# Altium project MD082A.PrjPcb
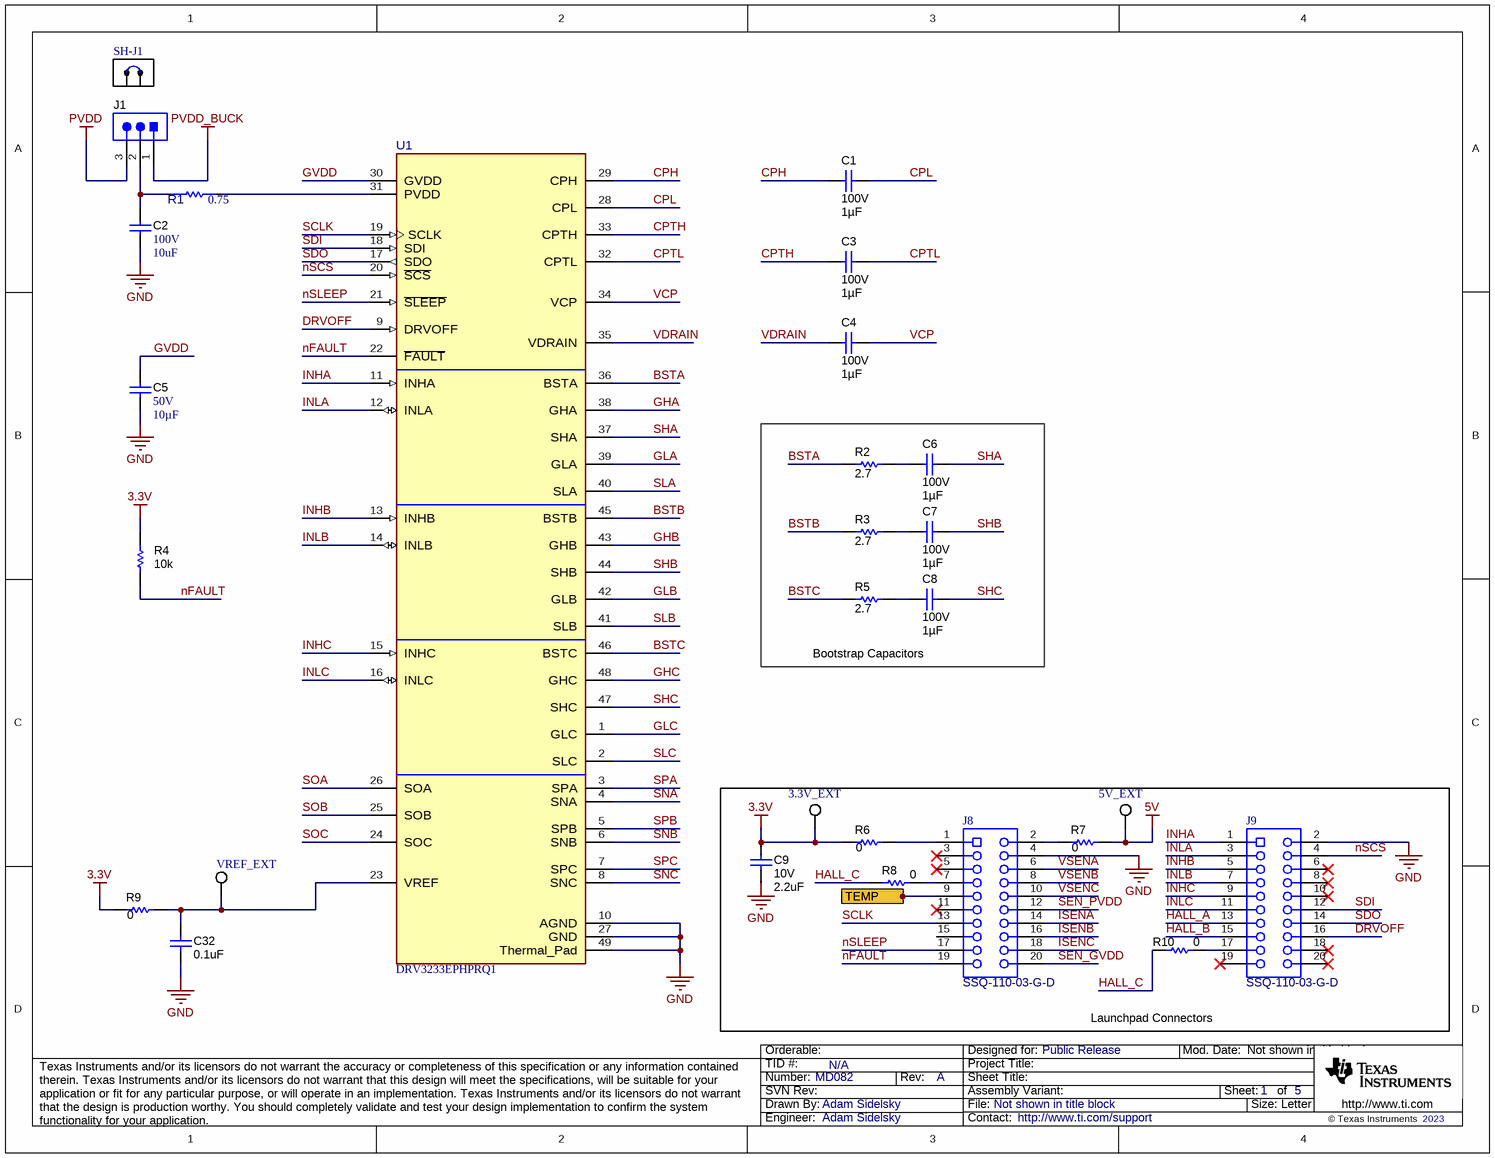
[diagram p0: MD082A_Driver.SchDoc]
CopyrightYear: 2023; DrawnBy: Adam Sidelsky; PCB_Layout: Adam Sidelsky; PCB_Rev: A; PRJ_Customer: Public Release; PRJ_Engineer: Adam Sidelsky; PRJ_Number: MD082; SCH_Rev: A; TechSupport: http://www.ti.com/support; TID: N/A
5 sheets, 201 parts. Net scope: global (net labels, ports and power ports of the same name join across sheets).
Board file: MD082A.PcbDoc
Sheets:
  MD082A_Driver.SchDoc
  MD082A_HalfBridges.SchDoc
  MD082A_Power.SchDoc
  MD082A_Hardware.SchDoc
  MD082A_SenseFeedback.SchDoc

## Sheet MD082A_Driver.SchDoc
size Letter; Date: Not shown in title block; ApprovedBy: Not shown in title block; CheckedBy: Not shown in title block; Author: Not shown in title block; CompanyName: Not shown in title block; Engineer: Not shown in title block; Organization: Not shown in title block; Address1: Not shown in title block; Address2: Not shown in title block; Address3: Not shown in title block; Address4: Not shown in title block; DocumentNumber: 1; Revision: Use project parameter SCH_Rev; SheetNumber: 1; SheetTotal: 5; PageSetup: Record=PageOptions¦CenterHorizontal=True¦CenterVertical=True¦PrintScale=1.00¦XCorrection=1.00¦YCorrection=1.00¦PrintKind=0¦BorderSize=5000000¦LeftOffset=0¦BottomOffset=0¦Orientation=2¦PaperLength=1000¦PaperWidth=1000¦Scale=100¦PaperSource=15¦PrintQuality=600¦MediaType=1¦DitherType=10¦PaperKind=Letter¦PrintScaleMode=1

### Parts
3.3V_EXT  5015  [Testpoint_Keystone_Miniature]  (value not drawn)
5V_EXT  5015  [Testpoint_Keystone_Miniature]  (value not drawn)
C1  VDC_V: 100V  Cap_F: 1µF  [0805_150]  (hidden comment: KAF21KR72A105KU)
C2  VDC_V: 100V  ValueDisplayed: 10uF  [2220_280L]  (hidden comment: CGA9N3X7S2A106K230KE)
C3  VDC_V: 100V  Cap_F: 1µF  [0805_150]  (hidden comment: KAF21KR72A105KU)
C4  VDC_V: 100V  Cap_F: 1µF  [0805_150]  (hidden comment: KAF21KR72A105KU)
C5  VDC_V: 50V  ValueDisplayed: 10µF  [1210_270L]  (hidden comment: CL32B106KBJNNWE)
C6  VDC_V: 100V  Cap_F: 1µF  [0805_150]  (hidden comment: KAF21KR72A105KU)
C7  VDC_V: 100V  Cap_F: 1µF  [0805_150]  (hidden comment: KAF21KR72A105KU)
C8  VDC_V: 100V  Cap_F: 1µF  [0805_150]  (hidden comment: KAF21KR72A105KU)
C9  VDC_V: 10V  ValueDisplayed: 2.2uF  [0402L]  (hidden comment: C1005X5R1A225K050BC)
C32  ValueDisplayed: 0.1uF  [0603L]  (hidden comment: C0603C104J4RAC7867)
J1  61300311121  [WURTH_61300311121]  (value not drawn)
J8  SSQ-110-03-G-D  [Samtec_SSQ-110-03-x-D]
J9  SSQ-110-03-G-D  [Samtec_SSQ-110-03-x-D]
R1  value 0.75  [FP-RL1220S-R75-F_0805-IPC_A]  (hidden comment: RL1220S-R75-F)
R2  ValueDisplayed: 2.7  [0805L]  (hidden comment: CRCW08052R70JNEA)
R3  ValueDisplayed: 2.7  [0805L]  (hidden comment: CRCW08052R70JNEA)
R4  value 10k  [0603L]  (hidden comment: CRCW060310K0JNEA)
R5  ValueDisplayed: 2.7  [0805L]  (hidden comment: CRCW08052R70JNEA)
R6  ValueDisplayed: 0  [0603L]  (hidden comment: RCS06030000Z0EA)
R7  ValueDisplayed: 0  [0603L]  (hidden comment: RCS06030000Z0EA)
R8  ValueDisplayed: 0  [0603L]  (hidden comment: RCS06030000Z0EA)
R9  ValueDisplayed: 0  [0603L]  (hidden comment: RCS06030000Z0EA)
R10  ValueDisplayed: 0  [0603L]  (hidden comment: RCS06030000Z0EA)
SH-J1  SNT-100-BK-G  [SNT-100-BK-G]  (value not drawn)
U1  DRV3233EPHPRQ1  [0-MFG]
VREF_EXT  5015  [Testpoint_Keystone_Miniature]  (value not drawn)

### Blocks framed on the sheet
Bootstrap Capacitors: C6-C8 R2 R3 R5
Launchpad Connectors: 3.3V_EXT 5V_EXT C9 J8 J9 R6-R8 R10

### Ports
TEMP (out)

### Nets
3.3V: 3.3V_EXT.1 C9.2 R4.1 R6.1 R9.1
5V: 5V_EXT.1 R7.2
GND: C2.2 C5.2 C9.1 C32.2 J8.4 J9.2 U1.10(AGND) U1.27(GND) U1.49(Thermal_Pad)
GVDD: C5.1 U1.30(GVDD)
PVDD: J1.3
PVDD_BUCK: J1.1
BSTA: R2.2 U1.36(BSTA)
BSTB: R3.2 U1.45(BSTB)
BSTC: R5.2 U1.46(BSTC)
CPH: C1.1 U1.29(CPH)
CPL: C1.2 U1.28(CPL)
CPTH: C3.1 U1.33(CPTH)
CPTL: C3.2 U1.32(CPTL)
DRVOFF: J9.16 U1.9(DRVOFF)
GHA: U1.38(GHA)
GHB: U1.43(GHB)
GHC: U1.48(GHC)
GLA: U1.39(GLA)
GLB: U1.42(GLB)
GLC: U1.1(GLC)
HALL_A: J9.13
HALL_B: J9.15
HALL_C: R8.1 R10.1
INHA: J9.1 U1.11(INHA)
INHB: J9.5 U1.13(INHB)
INHC: J9.9 U1.15(INHC)
INLA: J9.3 U1.12(INLA)
INLB: J9.7 U1.14(INLB)
INLC: J9.11 U1.16(INLC)
ISENA: J8.14
ISENB: J8.16
ISENC: J8.18
nFAULT: J8.19 R4.2 U1.22(~{FAULT})
nSCS: J9.4 U1.20(~{SCS})
nSLEEP: J8.17 U1.21(~{SLEEP})
SCLK: J8.13 U1.19(SCLK)
SDI: J9.12 U1.18(SDI)
SDO: J9.14 U1.17(SDO)
SEN_GVDD: J8.20
SEN_PVDD: J8.12
SHA: C6.1 U1.37(SHA)
SHB: C7.1 U1.44(SHB)
SHC: C8.1 U1.47(SHC)
SLA: U1.40(SLA)
SLB: U1.41(SLB)
SLC: U1.2(SLC)
SNA: U1.4(SNA)
SNB: U1.6(SNB)
SNC: U1.8(SNC)
SOA: U1.26(SOA)
SOB: U1.25(SOB)
SOC: U1.24(SOC)
SPA: U1.3(SPA)
SPB: U1.5(SPB)
SPC: U1.7(SPC)
TEMP: J8.9 ; port TEMP
VCP: C4.1 U1.34(VCP)
VDRAIN: C4.2 U1.35(VDRAIN)
VSENA: J8.6
VSENB: J8.8
VSENC: J8.10
NetC2_1: C2.1 J1.2 R1.1
NetC6_2: C6.2 R2.1
NetC7_2: C7.2 R3.1
NetC8_2: C8.2 R5.1
NetC32_1: C32.1 R9.2 U1.23(VREF) VREF_EXT.1
NetJ8_1: J8.1 R6.2
NetJ8_2: J8.2 R7.1
NetJ8_7: J8.7 R8.2
NetJ9_17: J9.17 R10.2
NetR1_2: R1.2 U1.31(PVDD)

Not connected (* = marked no-connect by the designer): J8 3* 5* 11* 15; J9 6* 8* 10* 18* 19* 20*

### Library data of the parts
3.3V_EXT 5V_EXT VREF_EXT = CMP-0055152-2: Test Point, Miniature, SMT; Manufacturer: Keystone Electronics; CT: TRUE; Green_Lifecycle: Active; Green_REACh: Passed; CNHeader: FALSE
C1 C3 C4 C6-C8 = CMP-0861070-2: CAP, CERM, 1 µF, 100 V,+/- 10%, X7R, AEC-Q200 Grade 1, 0805; Manufacturer: AVX; SizeZ_mm: 1.5; Polarized: N; TaMax_C: 125°C; TaMin_C: -55°C; Value: 1uF; AEC Qualified: Y; U/M: EA; AEC Grade: 1; Cap_Case: 0805; SizeX_mm: 2; SizeArea_mm2: 2.5; SizeAreaWB_mm2: 6.75; AEC Category: Q200; SizeY_mm: 1.25
C2 = CMP-0064964-2: CAP, CERM, 10 uF, 100 V,+/- 10%, X7S, AEC-Q200 Grade 1, 2220; Manufacturer: TDK; TaMin_C: -55°C; Polarized: N; SizeAreaWB_mm2: 53.9; Value1: Unknown; U/M: EA; Value: 10uF; TaMax_C: 125°C; SizeZ_mm: 2.8; SizeX_mm: 5.7; SizeY_mm: 5; Cap_Case: 2220; SizeArea_mm2: 28.5; AEC Qualified: Y; Cap_F: 10µF; AEC Grade: 1; AEC Category: Q200
C5 = CMP-0079201-1: CAP, CERM, 10 µF, 50 V,+/- 10%, X7R, 1210; Manufacturer: Samsung Electro-Mechanics; TaMin_C: -55°C; ESR_ohm: 5m; Polarized: N; SizeAreaWB_mm2: 14.7; Value1: 0.005 ohm; U/M: EA; Value: 10uF; TaMax_C: 125°C; SizeZ_mm: 2.7; SizeX_mm: 3.2; SizeY_mm: 2.5; Cap_Case: 1210; SizeArea_mm2: 8; AEC Category: Q200
C9 = CMP-0006263-2: CAP, CERM, 2.2 uF, 10 V, +/- 10%, X5R, 0402; Manufacturer: TDK; TaMin_C: -55°C; Polarized: N; SizeAreaWB_mm2: 3; Value1: Unknown; U/M: EA; Value: 2.2uF; TaMax_C: 85°C; SizeZ_mm: 0.6; SizeX_mm: 1; SizeY_mm: 0.5; Cap_Case: 0402; Cap_F: 2.2µF; AEC Category: Q200
C32 = CMP-0006857-5: CAP, CERM, 0.1 uF, 16 V, +/- 5%, X7R, 0603; Manufacturer: Kemet; Polarized: N; Value: 0.1uF; U/M: EA; Cap_F: 100nF; Value1: Unknown; VDC_V: 16V; TaMin_C: -55°C; TaMax_C: 125°C; Cap_Case: 0603; AEC Category: Q200; SizeArea_mm2: 1.28; SizeAreaWB_mm2: 4.68; SizeX_mm: 1.6; SizeY_mm: 0.8; SizeZ_mm: 1
J1 = CMP-0054796-4: Header, 2.54 mm, 3x1, Gold, TH; Manufacturer: Wurth Elektronik; Green_Lifecycle: Active; Green_REACh: Passed; CNHeader: TRUE; CT: FALSE
J8 J9 = CMP-0075613-1: Receptacle, 2.54mm, 10x2, Gold, TH; Manufacturer: Samtec; Pitch_mm: 2.54; Cert_VDE: N; Gender: Female; Cert_CSA: Y; Current_A: 6.3A; Voltage_V: 550V; CT: True; Row_Count: 2; CompType: Socket Strip; CNHeader: False
R1 = CMP-0096837-1: 750 mOhms ±1% 0.333W, 1/3W Chip Resistor 0805 (2012 Metric) Current Sense Thin Film; Manufacturer: Susumu; SizeZ_mm: 0.5mm; TempCo: 0/+200ppm/°C; Power_W: 333mW; AEC Qualified: No
R2 R3 R5 = CMP-0020521-3: RES, 2.7, 5%, 0.125 W, AEC-Q200 Grade 0, 0805; Manufacturer: Vishay-Dale; Power_W: 125mW; TempCo: 200 ppm/C; Value_Code: 2R70; Value: 2.7; EIA_Code: E24; SizeX_mm: 2; SizeY_mm: 1.25; SizeZ_mm: 1.45; Value2: 0.125W; SizeArea_mm2: 2.5; AEC Qualified: Y; VDC_V: 150V; AEC Category: Q200; AEC Grade: 0
R4 = CMP-0025701-4: RES, 10 k, 5%, 0.1 W, AEC-Q200 Grade 0, 0603; Manufacturer: Vishay-Dale; Value_Code: 10k0; Power_W: 100mW; Value2: 0.1W; VDC_V: 75V; TempCo: 200 ppm/C; EIA_Code: E24; AEC Category: Q200; AEC Qualified: Y; AEC Grade: 0; SizeArea_mm2: 1.28; SizeX_mm: 1.6; SizeY_mm: 0.8; SizeZ_mm: 1
R6-R10 = CMP-0081973-1: RES, 0, 0%, 0.25 W, AEC-Q200 Grade 0, 0603; Manufacturer: Vishay-Dale; SizeAreaWB_mm2: 4.68; SizeArea_mm2: 1.28; AEC Qualified: Y; AEC Category: Q200; Value: 0; SizeZ_mm: 1; SizeY_mm: 0.8; Power_W: 250mW; Value2: 0.25W; SizeX_mm: 1.6
SH-J1 = CMP-0003623-3: Shunt, 100mil, Gold plated, Black; Alternate PartNumber: 969102-0000-DA; Manufacturer: Samtec; Alternate Manufacturer: 3M; Value: 1x2
U1 = CMP-0097571-1: 12-V / 24-V Automotive Gate Driver Unit (GDU) with enhanced diagnostics; Manufacturer: Texas Instruments; Standoff Height: 0.05mm; TJmax_C: +175°C; Min Supply Voltage: 4V; Number Of Outputs: 3; Max Supply Voltage: 60V; AEC Qualified: Yes; SizeZ_mm: 1.2mm; AEC Grade: Grade 0; TaMin_C: -40°C; TaMax_C: +150°C; Propagation Delay: 70ns

## Sheet MD082A_HalfBridges.SchDoc
size Letter; Date: Not shown in title block; ApprovedBy: Not shown in title block; CheckedBy: Not shown in title block; Author: Not shown in title block; CompanyName: Not shown in title block; Engineer: Not shown in title block; Organization: Not shown in title block; Address1: Not shown in title block; Address2: Not shown in title block; Address3: Not shown in title block; Address4: Not shown in title block; DocumentNumber: 2; Revision: Use project parameter SCH_Rev; SheetNumber: 2; SheetTotal: 5; PageSetup: Record=PageOptions¦CenterHorizontal=True¦CenterVertical=True¦PrintScale=1.00¦XCorrection=1.00¦YCorrection=1.00¦PrintKind=0¦BorderSize=5000000¦LeftOffset=0¦BottomOffset=0¦Orientation=2¦PaperLength=1000¦PaperWidth=1000¦Scale=100¦PaperSource=15¦PrintQuality=600¦MediaType=1¦DitherType=10¦PaperKind=Letter¦PrintScaleMode=1
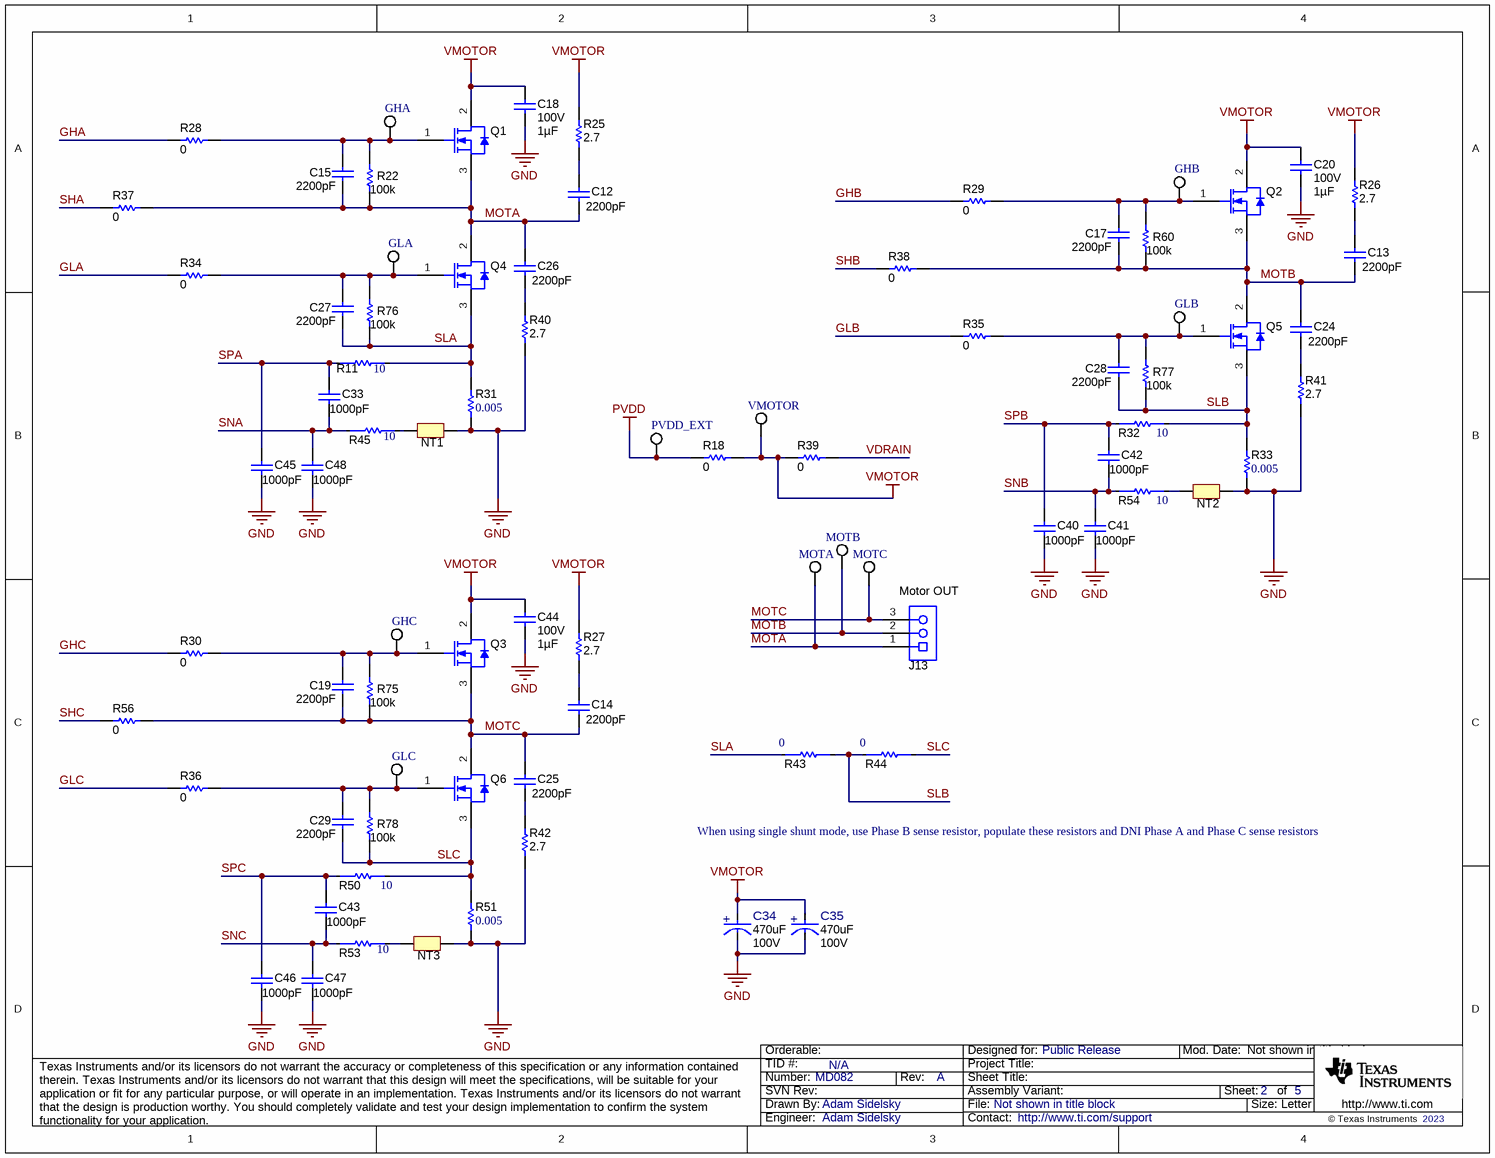
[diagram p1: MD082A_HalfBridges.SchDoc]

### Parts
C12  ValueDisplayed: 2200pF  [0603L]  (hidden comment: GRM188R72A222KA01D)
C13  ValueDisplayed: 2200pF  [0603L]  (hidden comment: GRM188R72A222KA01D)
C14  ValueDisplayed: 2200pF  [0603L]  (hidden comment: GRM188R72A222KA01D)
C15  ValueDisplayed: 2200pF  [0603L]  (hidden comment: 06031C222KAT2A)
C17  ValueDisplayed: 2200pF  [0603L]  (hidden comment: 06031C222KAT2A)
C18  VDC_V: 100V  Cap_F: 1µF  [0805_150]  (hidden comment: KAF21KR72A105KU)
C19  ValueDisplayed: 2200pF  [0603L]  (hidden comment: 06031C222KAT2A)
C20  VDC_V: 100V  Cap_F: 1µF  [0805_150]  (hidden comment: KAF21KR72A105KU)
C24  ValueDisplayed: 2200pF  [0603L]  (hidden comment: GRM188R72A222KA01D)
C25  ValueDisplayed: 2200pF  [0603L]  (hidden comment: GRM188R72A222KA01D)
C26  ValueDisplayed: 2200pF  [0603L]  (hidden comment: GRM188R72A222KA01D)
C27  ValueDisplayed: 2200pF  [0603L]  (hidden comment: 06031C222KAT2A)
C28  ValueDisplayed: 2200pF  [0603L]  (hidden comment: 06031C222KAT2A)
C29  ValueDisplayed: 2200pF  [0603L]  (hidden comment: 06031C222KAT2A)
C33  ValueDisplayed: 1000pF  [0603L]  (hidden comment: 885012206034)
C34  ValueDisplayed: 470uF  VDC_V: 100V  [FP-ESH477M100AM2AA_RADIAL-MFG]  (hidden comment: ESH477M100AM2AA)
C35  ValueDisplayed: 470uF  VDC_V: 100V  [FP-ESH477M100AM2AA_RADIAL-MFG]  (hidden comment: ESH477M100AM2AA)
C40  ValueDisplayed: 1000pF  [0603L]  (hidden comment: 885012206034)
C41  ValueDisplayed: 1000pF  [0603L]  (hidden comment: 885012206034)
C42  ValueDisplayed: 1000pF  [0603L]  (hidden comment: 885012206034)
C43  ValueDisplayed: 1000pF  [0603L]  (hidden comment: 885012206034)
C44  VDC_V: 100V  Cap_F: 1µF  [0805_150]  (hidden comment: KAF21KR72A105KU)
C45  ValueDisplayed: 1000pF  [0603L]  (hidden comment: 885012206034)
C46  ValueDisplayed: 1000pF  [0603L]  (hidden comment: 885012206034)
C47  ValueDisplayed: 1000pF  [0603L]  (hidden comment: 885012206034)
C48  ValueDisplayed: 1000pF  [0603L]  (hidden comment: 885012206034)
GHA  5015  [Testpoint_Keystone_Miniature]  (value not drawn)
GHB  5015  [Testpoint_Keystone_Miniature]  (value not drawn)
GHC  5015  [Testpoint_Keystone_Miniature]  (value not drawn)
GLA  5015  [Testpoint_Keystone_Miniature]  (value not drawn)
GLB  5015  [Testpoint_Keystone_Miniature]  (value not drawn)
GLC  5015  [Testpoint_Keystone_Miniature]  (value not drawn)
J13  Motor OUT  [Phoenix_1904150]
MOTA  5016  [Testpoint_Keystone_Compact]  (value not drawn)
MOTB  5016  [Testpoint_Keystone_Compact]  (value not drawn)
MOTC  5016  [Testpoint_Keystone_Compact]  (value not drawn)
NT1  Net-Tie  [Net-Tie_20milWide_60milLong]  (value not drawn)  (net tie, no BOM)
NT2  Net-Tie  [Net-Tie_20milWide_60milLong]  (value not drawn)  (net tie, no BOM)
NT3  Net-Tie  [Net-Tie_20milWide_60milLong]  (value not drawn)  (net tie, no BOM)
PVDD_EXT  5015  [Testpoint_Keystone_Miniature]  (value not drawn)
Q1  STH310N10F7-2  [DDPAK]  (value not drawn)
Q2  STH310N10F7-2  [DDPAK]  (value not drawn)
Q3  STH310N10F7-2  [DDPAK]  (value not drawn)
Q4  STH310N10F7-2  [DDPAK]  (value not drawn)
Q5  STH310N10F7-2  [DDPAK]  (value not drawn)
Q6  STH310N10F7-2  [DDPAK]  (value not drawn)
R11  value 10  [FP-CPF-A-0603B10RE_0603-MFG]  (hidden comment: CPF-A-0603B10RE)
R18  ValueDisplayed: 0  [0603L]  (hidden comment: RCS06030000Z0EA)
R22  ValueDisplayed: 100k  [0603L]  (hidden comment: CRCW0603100KFKEA)
R25  ValueDisplayed: 2.7  [0805L]  (hidden comment: CRCW08052R70JNEA)
R26  ValueDisplayed: 2.7  [0805L]  (hidden comment: CRCW08052R70JNEA)
R27  ValueDisplayed: 2.7  [0805L]  (hidden comment: CRCW08052R70JNEA)
R28  ValueDisplayed: 0  [0603L]  (hidden comment: RCS06030000Z0EA)
R29  ValueDisplayed: 0  [0603L]  (hidden comment: RCS06030000Z0EA)
R30  ValueDisplayed: 0  [0603L]  (hidden comment: RCS06030000Z0EA)
R31  ValueDisplayed: 0.005  [CRE2512-R5_R9]  (hidden comment: CRE2512-FZ-R005E-3)
R32  value 10  [FP-CPF-A-0603B10RE_0603-MFG]  (hidden comment: CPF-A-0603B10RE)
R33  ValueDisplayed: 0.005  [CRE2512-R5_R9]  (hidden comment: CRE2512-FZ-R005E-3)
R34  ValueDisplayed: 0  [0603L]  (hidden comment: RCS06030000Z0EA)
R35  ValueDisplayed: 0  [0603L]  (hidden comment: RCS06030000Z0EA)
R36  ValueDisplayed: 0  [0603L]  (hidden comment: RCS06030000Z0EA)
R37  ValueDisplayed: 0  [0603L]  (hidden comment: RCS06030000Z0EA)
R38  ValueDisplayed: 0  [0603L]  (hidden comment: RCS06030000Z0EA)
R39  ValueDisplayed: 0  [0603L]  (hidden comment: RCS06030000Z0EA)
R40  ValueDisplayed: 2.7  [0805L]  (hidden comment: CRCW08052R70JNEA)
R41  ValueDisplayed: 2.7  [0805L]  (hidden comment: CRCW08052R70JNEA)
R42  ValueDisplayed: 2.7  [0805L]  (hidden comment: CRCW08052R70JNEA)
R43  value 0  [FP-CRCW12060000Z0EAC_1206-MFG]  (hidden comment: CRCW12060000Z0EAC)
R44  value 0  [FP-CRCW12060000Z0EAC_1206-MFG]  (hidden comment: CRCW12060000Z0EAC)
R45  value 10  [FP-CPF-A-0603B10RE_0603-MFG]  (hidden comment: CPF-A-0603B10RE)
R50  value 10  [FP-CPF-A-0603B10RE_0603-MFG]  (hidden comment: CPF-A-0603B10RE)
R51  ValueDisplayed: 0.005  [CRE2512-R5_R9]  (hidden comment: CRE2512-FZ-R005E-3)
R53  value 10  [FP-CPF-A-0603B10RE_0603-MFG]  (hidden comment: CPF-A-0603B10RE)
R54  value 10  [FP-CPF-A-0603B10RE_0603-MFG]  (hidden comment: CPF-A-0603B10RE)
R56  ValueDisplayed: 0  [0603L]  (hidden comment: RCS06030000Z0EA)
R60  ValueDisplayed: 100k  [0603L]  (hidden comment: CRCW0603100KFKEA)
R75  ValueDisplayed: 100k  [0603L]  (hidden comment: CRCW0603100KFKEA)
R76  ValueDisplayed: 100k  [0603L]  (hidden comment: CRCW0603100KFKEA)
R77  ValueDisplayed: 100k  [0603L]  (hidden comment: CRCW0603100KFKEA)
R78  ValueDisplayed: 100k  [0603L]  (hidden comment: CRCW0603100KFKEA)
VMOTOR  5016  [Testpoint_Keystone_Compact]  (value not drawn)

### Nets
GND: C18.1 C20.1 C34.1(CATHODE) C35.1(CATHODE) C40.2 C41.2 C44.1 C45.2 C46.2 C47.2 C48.2 NT1.2 NT2.2 NT3.2 R31.1 R33.1 R40.1 R41.1 R42.1 R51.1
PVDD: PVDD_EXT.1 R18.2
VMOTOR: C18.2 C20.2 C34.2(ANODE) C35.2(ANODE) C44.2 Q1.2(D) Q2.2(D) Q3.2(D) R18.1 R25.2 R26.2 R27.2 R39.2 VMOTOR.1
GHA: R28.1
GHB: R29.1
GHC: R30.1
GLA: R34.1
GLB: R35.1
GLC: R36.1
MOTA: C12.2 C15.2 C26.1 J13.1 MOTA.1 Q1.3(S) Q4.2(D) R22.2 R37.2
MOTB: C13.2 C17.2 C24.1 J13.2 MOTB.1 Q2.3(S) Q5.2(D) R38.2 R60.2
MOTC: C14.2 C19.2 C25.1 J13.3 MOTC.1 Q3.3(S) Q6.2(D) R56.2 R75.2
SHA: R37.1
SHB: R38.1
SHC: R56.1
SLA: C27.2 Q4.3(S) R11.2 R31.2 R43.1 R76.2
SLB: C28.2 Q5.3(S) R32.2 R33.2 R43.2 R44.1 R77.2
SLC: C29.2 Q6.3(S) R44.2 R50.2 R51.2 R78.2
SNA: C33.2 C48.1 R45.1
SNB: C41.1 C42.2 R54.1
SNC: C43.2 C47.1 R53.1
SPA: C33.1 C45.1 R11.1
SPB: C40.1 C42.1 R32.1
SPC: C43.1 C46.1 R50.1
VDRAIN: R39.1
NetC12_1: C12.1 R25.1
NetC13_1: C13.1 R26.1
NetC14_1: C14.1 R27.1
NetC15_1: C15.1 GHA.1 Q1.1(G) R22.1 R28.2
NetC17_1: C17.1 GHB.1 Q2.1(G) R29.2 R60.1
NetC19_1: C19.1 GHC.1 Q3.1(G) R30.2 R75.1
NetC24_2: C24.2 R41.2
NetC25_2: C25.2 R42.2
NetC26_2: C26.2 R40.2
NetC27_1: C27.1 GLA.1 Q4.1(G) R34.2 R76.1
NetC28_1: C28.1 GLB.1 Q5.1(G) R35.2 R77.1
NetC29_1: C29.1 GLC.1 Q6.1(G) R36.2 R78.1
NetNT1_1: NT1.1 R45.2
NetNT2_1: NT2.1 R54.2
NetNT3_1: NT3.1 R53.2

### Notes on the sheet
- When using single shunt mode, use Phase B sense resistor, populate these resistors and DNI Phase A and Phase C sense resistors

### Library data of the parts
C12-C14 C24-C26 = CMP-0007475-4: CAP, CERM, 2200 pF, 100 V, +/- 10%, X7R, 0603; Manufacturer: MuRata; TaMin_C: -55°C; Polarized: N; SizeAreaWB_mm2: 4.68; Value1: Unknown; U/M: EA; Value: 2200pF; TaMax_C: 125°C; SizeZ_mm: 1; SizeX_mm: 1.6; SizeY_mm: 0.8; Cap_Case: 0603; Value2: 100V; SizeArea_mm2: 1.28; CompType: Capacitor; Cap_F: 2.2nF; AEC Category: Q200
C15 C17 C19 C27-C29 = CMP-0006737-4: CAP, CERM, 2200 pF, 100 V, +/- 10%, X7R, 0603; Manufacturer: AVX; TaMin_C: -55°C; ESR_ohm: 1.92d; Polarized: N; SizeAreaWB_mm2: 4.68; Value1: 0.192 ohm; U/M: EA; Value: 2200pF; TaMax_C: 125°C; SizeZ_mm: 1; SizeX_mm: 1.6; SizeY_mm: 0.8; Cap_Case: 0603; Value2: 100V; SizeArea_mm2: 1.28; CompType: Capacitor; Cap_F: 2.2nF; AEC Category: Q200
C18 C20 C44 = CMP-0861070-2: as C1 on sheet MD082A_Driver
C33 C40-C43 C45-C48 = CMP-0006826-4: CAP, CERM, 1000 pF, 16 V, +/- 10%, X7R, 0603; Manufacturer: Wurth Elektronik; TaMin_C: -55°C; Polarized: N; SizeAreaWB_mm2: 4.68; Value1: Unknown; U/M: EA; Value: 1000pF; TaMax_C: 125°C; SizeZ_mm: 1; SizeX_mm: 1.6; SizeY_mm: 0.8; Cap_Case: 0603; Value2: 16V; SizeArea_mm2: 1.28; CompType: Capacitor; Cap_F: 1nF; AEC Category: Q200
C34 C35 = CMP-0120361-1: 470 µF 100 V Aluminum Electrolytic Capacitors Radial, Can 2000 Hrs @ 105°C; Manufacturer: KEMET; AEC Qualified: No; Cap_F: 470µF; IRMS_A: 875mA; SizeZ_mm: 34mm; Tolerance_%: 20%; Dissipation Factor: 10%; Leakage Current: 470uA; Life: 2000Hours; Value: 470µF
GHA GHB GHC GLA GLB GLC PVDD_EXT = CMP-0055152-2: as 3.3V_EXT on sheet MD082A_Driver
J13 = CMP-0055528-1: Terminal Block, 9.52mm, 3x1, R/A, TH; PartNumber: 1904150; Manufacturer: Phoenix Contact; Pitch_mm: 9.52; Gender: Female; Row_Count: 1; Current_A: 32A; Voltage_V: 1kV; Cert_UL: Y; CNHeader: FALSE; CT: TRUE
MOTA MOTB MOTC VMOTOR = CMP-0055153-2: Test Point, Compact, SMT; Manufacturer: Keystone Electronics; Green_Lifecycle: Active; Green_REACh: Passed; CNHeader: FALSE; CT: TRUE
NT1-NT3 = CMP-0078142-6: Single point connection between nets.
Q1-Q6 = CMP-0001032-4: MOSFET, N-CH, 100 V, 180 A, DDPAK; Alternate Manufacturer: None; Manufacturer: STMicroelectronics; VdsMax_V: 100V; QgTyp_nC: 180; Value: 100V; SizeY_mm: 10.16; AEC Qualified: N; SizeX_mm: 15.245; Value2: 180 nC; IdsMax_A: 180A; SizeAreaWB_mm2: 209.6992; Vgs_V: 20V; ChMode: Enhancement; SizeZ_mm: 4.445; AEC Category: Q101; SizeArea_mm2: 154.8892
R11 R32 R45 R50 R53 R54 = CMP-0097543-1: 10 Ohms ±0.1% 0.063W, 1/16W Chip Resistor 0603 (1608 Metric) Anti-Sulfur, Automotive AEC-Q200, Moisture Resistant Thin Film; Manufacturer: TE Connectivity; VDC_V: 50V; AEC Grade: Grade 0; AEC Qualified: Yes; TempCo: 25ppm/°C; SizeZ_mm: 0.55mm; Power_W: 62.5mW
R18 R28-R30 R34-R39 R56 = CMP-0081973-1: as R6 on sheet MD082A_Driver
R22 R60 R75-R78 = CMP-0021990-4: RES, 100 k, 1%, 0.1 W, AEC-Q200 Grade 0, 0603; Manufacturer: Vishay-Dale; Power_W: 100mW; TempCo: 100 ppm/C; Value: 100k; EIA_Code: E96; SizeX_mm: 1.6; SizeY_mm: 0.8; SizeZ_mm: 1; Value2: 0.1W; SizeArea_mm2: 1.28; AEC Qualified: Y; VDC_V: 75V; AEC Category: Q200; AEC Grade: 0
R25-R27 R40-R42 = CMP-0020521-3: as R2 on sheet MD082A_Driver
R31 R33 R51 = CMP-0015751-2: RES, 0.005, 1%, 3 W, AEC-Q200 Grade 0, 2512; Manufacturer: Bourns; Power_W: 3W; TempCo: 75 ppm/C; Value_Code: 5L000; U/M: EA; Value: 0.005; EIA_Code: E96; Res_ohm: 5m; SizeX_mm: 6.45; SizeY_mm: 3.35; SizeZ_mm: 0.9; SizeArea_mm2: 21.6075; AEC Qualified: Y; AEC Grade: 0; AEC Category: Q200
R43 R44 = CMP-0094724-1: Jumper 0.25W, 1/4W Chip Resistor 1206 (3216 Metric) - Thick Film; Manufacturer: Vishay; SizeZ_mm: 0.65mm; Power_W: 250mW; VDC_V: 200V; AEC Qualified: No

## Sheet MD082A_Power.SchDoc
size Letter; Date: Not shown in title block; ApprovedBy: Not shown in title block; CheckedBy: Not shown in title block; Author: Not shown in title block; CompanyName: Not shown in title block; Engineer: Not shown in title block; Organization: Not shown in title block; Address1: Not shown in title block; Address2: Not shown in title block; Address3: Not shown in title block; Address4: Not shown in title block; DocumentNumber: 4; Revision: Use project parameter SCH_Rev; SheetNumber: 4; SheetTotal: 5; PageSetup: Record=PageOptions¦CenterHorizontal=True¦CenterVertical=True¦PrintScale=1.00¦XCorrection=1.00¦YCorrection=1.00¦PrintKind=0¦BorderSize=5000000¦LeftOffset=0¦BottomOffset=0¦Orientation=2¦PaperLength=1000¦PaperWidth=1000¦Scale=100¦PaperSource=15¦PrintQuality=600¦MediaType=1¦DitherType=10¦PaperKind=Letter¦PrintScaleMode=1
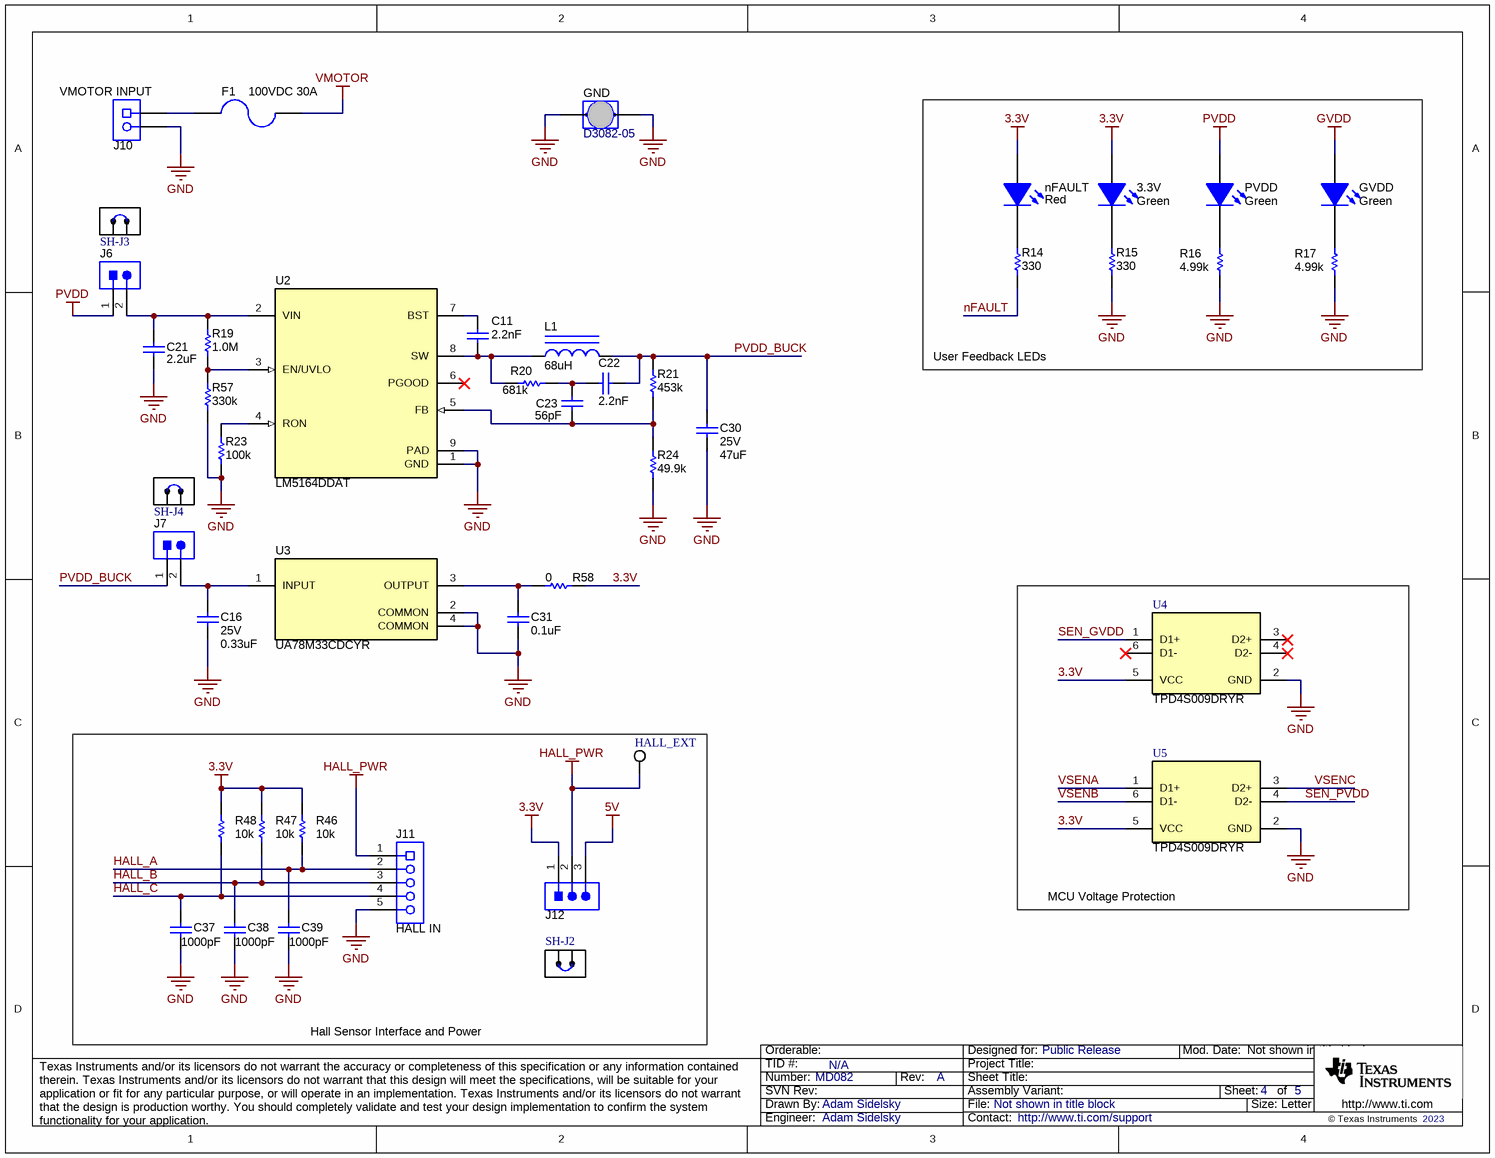
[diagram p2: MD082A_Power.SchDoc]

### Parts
3.3V  value Green  [LED_LTST-C171]
C11  Cap_F: 2.2nF  [0603L]  (hidden comment: CGA3E2X7R2A222K080AA)
C16  VDC_V: 25V  ValueDisplayed: 0.33uF  [0805L]  (hidden comment: KGM21AR51E334KU)
C21  ValueDisplayed: 2.2uF  [1210_210L]  (hidden comment: C1210C225K1RAC7800)
C22  Cap_F: 2.2nF  [0603L]  (hidden comment: CGA3E2X7R2A222K080AA)
C23  ValueDisplayed: 56pF  [0603L]  (hidden comment: GRM1885C2A560JA01D)
C30  VDC_V: 25V  ValueDisplayed: 47uF  [1206_190L]  (hidden comment: C3216X5R1E476M160AC)
C31  ValueDisplayed: 0.1uF  [0603L]  (hidden comment: C0603C104J4RAC7867)
C37  ValueDisplayed: 1000pF  [0603L]  (hidden comment: 885012206034)
C38  ValueDisplayed: 1000pF  [0603L]  (hidden comment: 885012206034)
C39  ValueDisplayed: 1000pF  [0603L]  (hidden comment: 885012206034)
F1  100VDC 30A  [Fuse_0463]
GND  D3082-05  [Harwin_D3082-05]
GVDD  value Green  [LED_LTST-C171]
HALL_EXT  5015  [Testpoint_Keystone_Miniature]  (value not drawn)
J6  PBC02SAAN  [Sullins_PBC02SAAN]  (value not drawn)
J7  PBC02SAAN  [Sullins_PBC02SAAN]  (value not drawn)
J10  VMOTOR INPUT  [Phoenix_1902547]
J11  HALL IN  [Phoenix_1792892]
J12  61300311121  [WURTH_61300311121]  (value not drawn)
L1  ValueDisplayed: 68uH  [SDR1006]  (hidden comment: SDR1006-680KL)
nFAULT  value Red  [LED_LTST-C170_Red]
PVDD  value Green  [LED_LTST-C171]
R14  ValueDisplayed: 330  [0603L]  (hidden comment: CRCW0603330RJNEA)
R15  ValueDisplayed: 330  [0603L]  (hidden comment: CRCW0603330RJNEA)
R16  value 4.99k  [0603L]  (hidden comment: CRCW06034K99FKEA)
R17  value 4.99k  [0603L]  (hidden comment: CRCW06034K99FKEA)
R19  ValueDisplayed: 1.0M  [0603L]  (hidden comment: CRCW06031M00JNEA)
R20  ValueDisplayed: 681k  [0603L]  (hidden comment: RC0603FR-07681KL)
R21  ValueDisplayed: 453k  [0603L]  (hidden comment: RC0603FR-07453KL)
R23  ValueDisplayed: 100k  [0402L]  (hidden comment: CRCW0402100KFKED)
R24  ValueDisplayed: 49.9k  [0603L]  (hidden comment: RC0603FR-0749K9L)
R46  value 10k  [0603L]  (hidden comment: CRCW060310K0JNEA)
R47  value 10k  [0603L]  (hidden comment: CRCW060310K0JNEA)
R48  value 10k  [0603L]  (hidden comment: CRCW060310K0JNEA)
R57  ValueDisplayed: 330k  [0603L]  (hidden comment: CRCW0603330KJNEA)
R58  value 0  [0603L]  (hidden comment: CRCW06030000Z0EA)
SH-J2  SNT-100-BK-G  [SNT-100-BK-G]  (value not drawn)
SH-J3  SNT-100-BK-G  [SNT-100-BK-G]  (value not drawn)
SH-J4  SNT-100-BK-G  [SNT-100-BK-G]  (value not drawn)
U2  LM5164DDAT  [DDA0008E_N]
U3  UA78M33CDCYR  [DCY0004A_N]
U4  TPD4S009DRYR  [DRY0006A]
U5  TPD4S009DRYR  [DRY0006A]

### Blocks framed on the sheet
User Feedback LEDs: 3.3V GVDD nFAULT PVDD R14-R17
MCU Voltage Protection: U4 U5
Hall Sensor Interface and Power: C37-C39 HALL_EXT J11 J12 R46-R48 SH-J2

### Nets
3.3V: 3.3V.1(A) J12.1 nFAULT.1(A) R46.1 R47.1 R48.1 R58.2 U4.5(VCC) U5.5(VCC)
5V: J12.3
GND: C16.2 C21.2 C30.2 C31.2 C37.2 C38.2 C39.2 GND.1 GND.2 J10.2 J11.5 R15.1 R16.1 R17.1 R23.1 R24.1 R57.1 U2.1(GND) U2.9(PAD) U3.2(COMMON) U3.4(COMMON) U4.2(GND) U5.2(GND)
GVDD: GVDD.1(A)
HALL_PWR: HALL_EXT.1 J11.1 J12.2
PVDD: J6.1 PVDD.1(A)
PVDD_BUCK: C22.1 C30.1 J7.1 L1.2 R21.2
VMOTOR: F1.1
HALL_A: C39.1 J11.2 R46.2
HALL_B: C38.1 J11.3 R47.2
HALL_C: C37.1 J11.4 R48.2
nFAULT: R14.1
SEN_GVDD: U4.1(D1+)
SEN_PVDD: U5.4(D2-)
VSENA: U5.1(D1+)
VSENB: U5.6(D1-)
VSENC: U5.3(D2+)
Net3.3V_2: 3.3V.2(K) R15.2
NetC11_1: C11.1 U2.7(BST)
NetC11_2: C11.2 L1.1 R20.1 U2.8(SW)
NetC16_1: C16.1 J7.2 U3.1(INPUT)
NetC21_1: C21.1 J6.2 R19.2 U2.2(VIN)
NetC22_2: C22.2 C23.1 R20.2
NetC23_2: C23.2 R21.1 R24.2 U2.5(FB)
NetC31_1: C31.1 R58.1 U3.3(OUTPUT)
NetF1_2: F1.2 J10.1
NetGVDD_2: GVDD.2(K) R17.2
NetnFAULT_2: nFAULT.2(K) R14.2
NetPVDD_2: PVDD.2(K) R16.2
NetR19_1: R19.1 R57.2 U2.3(EN/UVLO)
NetR23_2: R23.2 U2.4(RON)

Not connected (* = marked no-connect by the designer): U2 6(PGOOD)*; U4 3(D2+)* 4(D2-)* 6(D1-)*

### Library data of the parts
3.3V GVDD PVDD = CMP-0002830-3: LED, Green, SMD; Manufacturer: Lite-On; PartNumber: LTST-C171GKT; Vf_V: 2.1V; Io_A: 20A; Value1: W; SizeArea_mm2: 2.5; SizeAreaWB_mm2: 6.75; SizeX_mm: 2; SizeY_mm: 1.25; SizeZ_mm: 1.2
C11 C22 = CMP-0007085-4: CAP, CERM, 2200 pF, 100 V, +/- 10%, X7R, AEC-Q200 Grade 1, 0603; Manufacturer: TDK; TaMin_C: -55°C; ESR_ohm: 0.923948; Polarized: N; SizeAreaWB_mm2: 4.68; Value1: 0.923948 ohm; U/M: EA; Value: 2200pF; TaMax_C: 125°C; SizeZ_mm: 1; SizeX_mm: 1.6; SizeY_mm: 0.8; Cap_Case: 0603; Value2: 100V; SizeArea_mm2: 1.28; AEC Qualified: Y; IRMS_A: 295.638mA; AEC Category: Q200
C16 = CMP-0007575-3: CAP, CERM, 0.33 uF, 25 V, +/- 10%, X5R, 0805; Manufacturer: AVX; TaMin_C: -55°C; ESR_ohm: 20m; Polarized: N; SizeAreaWB_mm2: 6.75; Value1: 0.02 ohm; U/M: EA; Value: 0.33uF; TaMax_C: 85°C; SizeZ_mm: 1.45; SizeX_mm: 2; SizeY_mm: 1.25; Cap_Case: 0805; SizeArea_mm2: 2.5; Cap_F: 330nF; AEC Category: Q200
C21 = CMP-0009084-2: CAP, CERM, 2.2 uF, 100 V, +/- 10%, X7R, 1210; Manufacturer: Kemet; TaMin_C: -55°C; Polarized: N; SizeAreaWB_mm2: 14.7; Value1: Unknown; U/M: EA; Value: 2.2uF; TaMax_C: 125°C; SizeZ_mm: 2.1; SizeX_mm: 3.2; SizeY_mm: 2.5; Cap_Case: 1210; Value2: 100V; SizeArea_mm2: 8; Cap_F: 2.2µF; AEC Category: Q200
C23 = CMP-0007275-4: CAP, CERM, 56 pF, 100 V, +/- 5%, C0G/NP0, 0603; Manufacturer: MuRata; TaMin_C: -55°C; Polarized: N; SizeAreaWB_mm2: 4.68; Value1: Unknown; U/M: EA; Value: 56pF; TaMax_C: 125°C; SizeZ_mm: 1; SizeX_mm: 1.6; SizeY_mm: 0.8; Cap_Case: 0603; Value2: 100V; SizeArea_mm2: 1.28; AEC Category: Q200
C30 = CMP-0008656-2: CAP, CERM, 47 uF, 25 V, +/- 20%, X5R, 1206_190; Manufacturer: TDK; TaMin_C: -55°C; Polarized: N; SizeAreaWB_mm2: 10.92; Value1: Unknown; U/M: EA; Value: 47uF; TaMax_C: 85°C; SizeZ_mm: 1.9; SizeX_mm: 3.2; SizeY_mm: 1.6; Cap_Case: 1206; SizeArea_mm2: 5.12; Cap_F: 47µF; AEC Category: Q200
C31 = CMP-0006857-5: as C32 on sheet MD082A_Driver
C37-C39 = CMP-0006826-4: as C33 on sheet MD082A_HalfBridges
F1 = CMP-0077200-3: Fuse, 30 A, 250 VAC, 100 VDC, SMD; PartNumber: 0463030.ER; Manufacturer: Littelfuse; VAC_V: 250V; SizeAreaWB_mm2: 61.952; Rtyp_Ohm: 1.93m; SizeArea_mm2: 31.512; MeltingTyp: 916; SizeZ_mm: 3.12; VDC_V: 100V; SizeX_mm: 10.1; Interrupt_AC: 100A; Interrupt_DC: 50A; Fuse Speed: Fast; Fuse Technology: Board Mount; TaMax_C: 125°C; TaMin_C: -55°C
GND = CMP-0075110-1: 1mm Uninsulated Shorting Plug, 10.16mm spacing, TH; Manufacturer: Harwin; CNHeader: False; Green_Lifecycle: Active; Green_REACh: Passed; CompType: Jumper Wire
HALL_EXT = CMP-0055152-2: as 3.3V_EXT on sheet MD082A_Driver
J6 J7 = CMP-0054566-1: Header, 100mil, 2x1, Gold, TH; Manufacturer: Sullins Connector Solutions; CNHeader: TRUE; Current_A: 3A; Green_Lifecycle: Active; Shrouded: N; Gender: Male; Green_REACh: Passed; Voltage_V: 1.8kV; Row_Count: 1; Pitch_mm: 2.54; CT: FALSE; Cert_UL: Y
J10 = CMP-0055527-1: Terminal Block, 9.52mm, 2x1, R/A, TH; PartNumber: 1902547; Manufacturer: Phoenix Contact; Pitch_mm: 9.52; Gender: Female; Row_Count: 1; Current_A: 32A; Voltage_V: 1kV; Cert_UL: Y; CNHeader: FALSE; CT: TRUE
J11 = CMP-0055532-1: Terminal Block, 5mm, 5x1, R/A, TH; Manufacturer: Phoenix Contact; PartNumber: 1792892; Cert_VDE: Y; CNHeader: FALSE; Current_A: 16A; Gender: Female; Voltage_V: 400V; Row_Count: 1; Pitch_mm: 5; CT: TRUE
J12 = CMP-0054796-4: as J1 on sheet MD082A_Driver
L1 = CMP-0057541-2: Inductor, Drum Core, Ferrite, 68 uH, 1.1 A, 0.22 ohm, SMD; Manufacturer: Bourns; Isat: 2A @ 10% inductance drop; Irms: 1.1A @ 40C rise; Green_Lifecycle: Active; SizeAreaWB_mm2: 139.24; DCR_ohm: 0.22; Green_REACh: Passed; Value: 68uH; Imax_A: 1.1A; SizeZ_mm: 5.8; SizeX_mm: 9.8; SizeArea_mm2: 96.04; Ind_H: 68µH; AEC Category: Q200
nFAULT = CMP-0002829-3: LED, Red, SMD; Manufacturer: Lite-On; PartNumber: LTST-C170KRKT; Io_A: 20mA; SizeAreaWB_mm2: 6.75; Value1: W; SizeZ_mm: 1.2; SizeX_mm: 2; SizeY_mm: 1.25; Vf_V: 2V; SizeArea_mm2: 2.5
R14 R15 = CMP-0025785-4: RES, 330, 5%, 0.1 W, AEC-Q200 Grade 0, 0603; Manufacturer: Vishay-Dale; Power_W: 100mW; TempCo: 200 ppm/C; Value_Code: 330R; Value: 330; EIA_Code: E24; SizeX_mm: 1.6; SizeY_mm: 0.8; SizeZ_mm: 1; Value2: 0.1W; SizeArea_mm2: 1.28; CompType: Resistor; AEC Qualified: Y; VDC_V: 75V; AEC Category: Q200; AEC Grade: 0
R16 R17 = CMP-0022458-4: RES, 4.99 k, 1%, 0.1 W, AEC-Q200 Grade 0, 0603; Manufacturer: Vishay-Dale; Value_Code: 4k99; Power_W: 100mW; Value2: 0.1W; VDC_V: 75V; TempCo: 100 ppm/C; EIA_Code: E96; AEC Category: Q200; AEC Qualified: Y; AEC Grade: 0; SizeArea_mm2: 1.28; SizeX_mm: 1.6; SizeY_mm: 0.8; SizeZ_mm: 1
R19 = CMP-0025736-4: RES, 1.0 M, 5%, 0.1 W, AEC-Q200 Grade 0, 0603; Manufacturer: Vishay-Dale; Power_W: 100mW; TempCo: 200 ppm/C; Value_Code: 1M00; Value: 1.0Meg; EIA_Code: E24; Res_ohm: 1M; SizeX_mm: 1.6; SizeY_mm: 0.8; SizeZ_mm: 1; Value2: 0.1W; SizeArea_mm2: 1.28; AEC Qualified: Y; VDC_V: 75V; AEC Category: Q200; AEC Grade: 0
R20 = CMP-0023236-4: RES, 681 k, 1%, 0.1 W, 0603; Manufacturer: Yageo; Power_W: 100mW; TempCo: 100 ppm/C; Value: 681k; EIA_Code: E96; SizeX_mm: 1.6; SizeY_mm: 0.8; SizeZ_mm: 1; Value2: 0.1W; SizeArea_mm2: 1.28; AEC Qualified: N; VDC_V: 75V; AEC Category: Q200; SizeAreaWB_mm2: 4.68
R21 = CMP-0023120-4: RES, 453 k, 1%, 0.1 W, 0603; Manufacturer: Yageo; Power_W: 100mW; TempCo: 100 ppm/C; Value: 453k; EIA_Code: E96; SizeX_mm: 1.6; SizeY_mm: 0.8; SizeZ_mm: 1; Value2: 0.1W; SizeArea_mm2: 1.28; AEC Qualified: N; VDC_V: 75V; AEC Category: Q200; SizeAreaWB_mm2: 4.68
R23 = CMP-0025950-3: RES, 100 k, 1%, 0.063 W, AEC-Q200 Grade 0, 0402; Manufacturer: Vishay-Dale; Power_W: 63mW; TempCo: 100 ppm/C; Value: 100k; EIA_Code: E96; SizeX_mm: 1; SizeY_mm: 0.5; SizeZ_mm: 0.6; Value2: 0.063W; AEC Qualified: Y; VDC_V: 50V; AEC Category: Q200; AEC Grade: 0
R24 = CMP-0023142-5: RES, 49.9 k, 1%, 0.1 W, 0603; Manufacturer: Yageo; Power_W: 100mW; TempCo: 100 ppm/C; Value_Code: 49k9; Value: 49.9k; EIA_Code: E96; SizeX_mm: 1.6; SizeY_mm: 0.8; SizeZ_mm: 1; Value2: 0.1W; SizeArea_mm2: 1.28; AEC Qualified: N; VDC_V: 75V; AEC Category: Q200; SizeAreaWB_mm2: 4.68
R46-R48 = CMP-0025701-4: as R4 on sheet MD082A_Driver
R57 = CMP-0025784-4: RES, 330 k, 5%, 0.1 W, AEC-Q200 Grade 0, 0603; Manufacturer: Vishay-Dale; Power_W: 100mW; TempCo: 200 ppm/C; Value: 330k; EIA_Code: E24; SizeX_mm: 1.6; SizeY_mm: 0.8; SizeZ_mm: 1; Value2: 0.1W; SizeArea_mm2: 1.28; AEC Qualified: Y; VDC_V: 75V; AEC Category: Q200; AEC Grade: 0
R58 = CMP-0025697-4: RES, 0, 5%, 0.1 W, AEC-Q200 Grade 0, 0603; Manufacturer: Vishay-Dale; Value_Code: 0000; Power_W: 100mW; Value2: 0.1W; VDC_V: 75V; TempCo: 200 ppm/C; EIA_Code: E24; AEC Category: Q200; AEC Qualified: Y; SizeArea_mm2: 1.28; SizeX_mm: 1.6; SizeY_mm: 0.8; SizeZ_mm: 1
SH-J2-SH-J4 = CMP-0003623-3: as SH-J1 on sheet MD082A_Driver
U2 = CMP-0080798-1: 100-V Low IQ Synchronous Buck Regulator, DDA0008E (SOIC-8); Alternate Manufacturer: Texas Instruments; SizeAreaWB_mm2: 57.4; SizeZ_mm: 1.7; SizeX_mm: 5; SizeY_mm: 6.2; SizeArea_mm2: 31; CompType: IC; AEC Qualified: N; AEC Category: Q200
U3 = CMP-0080825-1: 500-mA, 25-V, Linear Voltage Regulators, DCY0004A (SOT-223-4); Alternate Manufacturer: Texas Instruments; Green_Lifecycle: Active; SizeAreaWB_mm2: 76.5; Green_REACh: Passed; SizeZ_mm: 1.8; SizeX_mm: 7; SizeY_mm: 6.5; SizeArea_mm2: 45.5; CompType: IC; AEC Qualified: N; AEC Category: Q200
U4 U5 = CMP-0043120-3: 4-Channel ESD Solution for High-Speed Differential Interface, DRY0006A (USON-6); Manufacturer: Texas Instruments; Eco-Plan: Green (RoHS & no Sb/Br); Differential Capacitance(pF): 0.05; IEC 61000-4-2 Contact(+/- kV): 8; IO Capacitance(Typ)(pF): 0.8; Breakdown Voltage(Min)(V): 9; IO Leakage Current(nA): Jan-00; AEC Category: Q200; AEC Qualified: N; CompType: IC; SizeAreaWB_mm2: 4.9; SizeArea_mm2: 1.45; SizeX_mm: 1.0; SizeZ_mm: 0.6; Rating: Catalog

## Sheet MD082A_Hardware.SchDoc
size 431 x 279 mm; Date: Not shown in title block; ApprovedBy: Not shown in title block; CheckedBy: Not shown in title block; Author: Not shown in title block; CompanyName: Not shown in title block; Engineer: Not shown in title block; Organization: Not shown in title block; Address1: Not shown in title block; Address2: Not shown in title block; Address3: Not shown in title block; Address4: Not shown in title block; DocumentNumber: 5; Revision: Use project parameter SCH_Rev; SheetNumber: 5; SheetTotal: 5; PageSetup: Record=PageOptions¦CenterHorizontal=True¦CenterVertical=True¦PrintScale=1.00¦XCorrection=1.00¦YCorrection=1.00¦PrintKind=0¦BorderSize=5000000¦LeftOffset=0¦BottomOffset=0¦Orientation=2¦PaperLength=1000¦PaperWidth=1000¦Scale=100¦PaperSource=15¦PrintQuality=600¦MediaType=1¦DitherType=10¦PaperKind=Letter¦PrintScaleMode=1
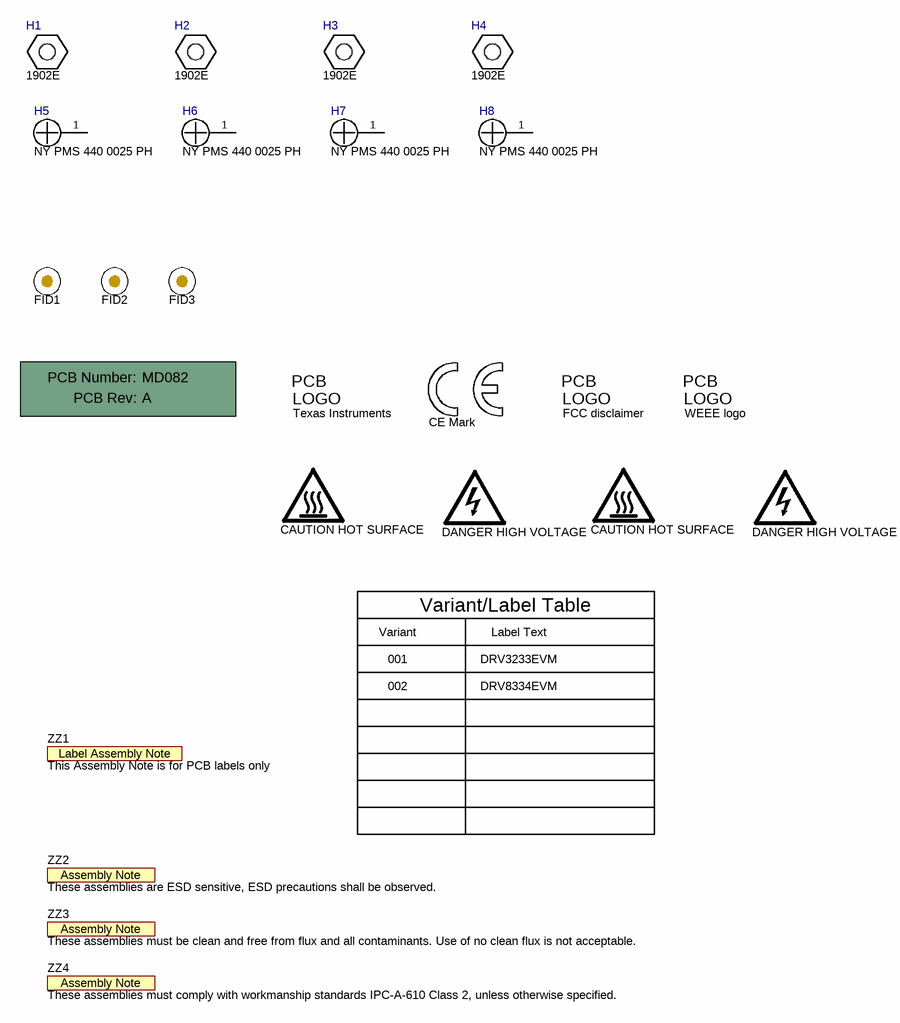
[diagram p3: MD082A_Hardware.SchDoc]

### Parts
!PCB1  Printed Circuit Board  (value not drawn)  (mechanical)
FID1  Fiducial  [Fiducial10-20]  (value not drawn)
FID2  Fiducial  [Fiducial10-20]  (value not drawn)
FID3  Fiducial  [Fiducial10-20]  (value not drawn)
H1  1902E  [Keystone_1902E]
H2  1902E  [Keystone_1902E]
H3  1902E  [Keystone_1902E]
H4  1902E  [Keystone_1902E]
H5  NY PMS 440 0025 PH  [NY PMS 440 0025 PH]
H6  NY PMS 440 0025 PH  [NY PMS 440 0025 PH]
H7  NY PMS 440 0025 PH  [NY PMS 440 0025 PH]
H8  NY PMS 440 0025 PH  [NY PMS 440 0025 PH]
Logo1  CE Mark  [CE_Mark_5mm]  (no BOM)
Logo2  Texas Instruments  [TI_Stacked_Overlay_Small]  (no BOM)
Logo3  FCC disclaimer  [FCC_disclaimer]  (no BOM)
Logo4  WEEE logo  [WEEE_Minimum]  (no BOM)
LOGO5  CAUTION HOT SURFACE  [IEC_HotSurface_Small]  (no BOM)
LOGO6  DANGER HIGH VOLTAGE  [IEC_HighVoltage_Small]  (no BOM)
LOGO7  CAUTION HOT SURFACE  [IEC_HotSurface_Small]  (no BOM)
LOGO8  DANGER HIGH VOLTAGE  [IEC_HighVoltage_Small]  (no BOM)
ZZ1  This Assembly Note is for PCB labels only  [AssemblyNoteLabel]  (no BOM)
ZZ2  These assemblies are ESD sensitive, ESD precautions shall be observed.  [AssemblyNote]  (no BOM)
ZZ3  These assemblies must be clean and free from flux and all contaminants. Use of no clean flux is not acceptable.  [AssemblyNote]  (no BOM)
ZZ4  These assemblies must comply with workmanship standards IPC-A-610 Class 2, unless otherwise specified.  [AssemblyNote]  (no BOM)

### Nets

Not connected (* = marked no-connect by the designer): H5 1; H6 1; H7 1; H8 1

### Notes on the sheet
- Variant
- Variant/Label Table
- Label Text
- 001
- 002
- DRV3233EVM
- DRV8334EVM

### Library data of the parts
!PCB1 = CMP-0003618-2: Manufacturer: Any; PartNumber: MD082
FID1-FID3 = CMP-0077181-1: Fiducial mark.  There is nothing to buy or mount.
H1-H4 = CMP-0003611-1: Manufacturer: Keystone; CompType: Hardware
H5-H8 = CMP-0003617-1: Machine Screw, Round, #4-40 x 1/4, Nylon, Philips panhead; Manufacturer: B&F Fastener Supply; CompType: Hardware
Logo1 = CMP-0074844-1: SymbolCreator: a0412235
Logo2 = CMP-0074838-1: Texas Instrument Corporate Signature; SymbolCreator: a0412235; Lib Reference: TI_Logo; Library Reference: Logo
Logo3 = CMP-0074847-1: FCC_disclaimer; Library Reference: Logo
Logo4 = CMP-0074769-3: Manufacturer: Texas Instruments; AEC Category: Q200; CompType: IC
LOGO5 LOGO7 = CMP-0074837-2: IEC 61010-1 Hot Surface Warning; Manufacturer: Texas Instruments; SymbolCreator: a0412235; AEC Category: Q200; CompType: IC
LOGO6 LOGO8 = CMP-0074835-1: IEC 61010-1 High Voltage Warning; SymbolCreator: a0412235; Lib Reference: IEC_HighVoltage
ZZ1 = CMP-0003616-3
ZZ2 = CMP-0077236-1
ZZ3 = CMP-0077237-1
ZZ4 = CMP-0077238-1

## Sheet MD082A_SenseFeedback.SchDoc
size Letter; Date: Not shown in title block; ApprovedBy: Not shown in title block; CheckedBy: Not shown in title block; Author: Not shown in title block; CompanyName: Not shown in title block; Engineer: Not shown in title block; Organization: Not shown in title block; Address1: Not shown in title block; Address2: Not shown in title block; Address3: Not shown in title block; Address4: Not shown in title block; DocumentNumber: 3; Revision: Use project parameter SCH_Rev; SheetNumber: 3; SheetTotal: 5; PageSetup: Record=PageOptions¦CenterHorizontal=True¦CenterVertical=True¦PrintScale=1.00¦XCorrection=1.00¦YCorrection=1.00¦PrintKind=0¦BorderSize=5000000¦LeftOffset=0¦BottomOffset=0¦Orientation=2¦PaperLength=1000¦PaperWidth=1000¦Scale=100¦PaperSource=15¦PrintQuality=600¦MediaType=1¦DitherType=10¦PaperKind=Letter¦PrintScaleMode=1
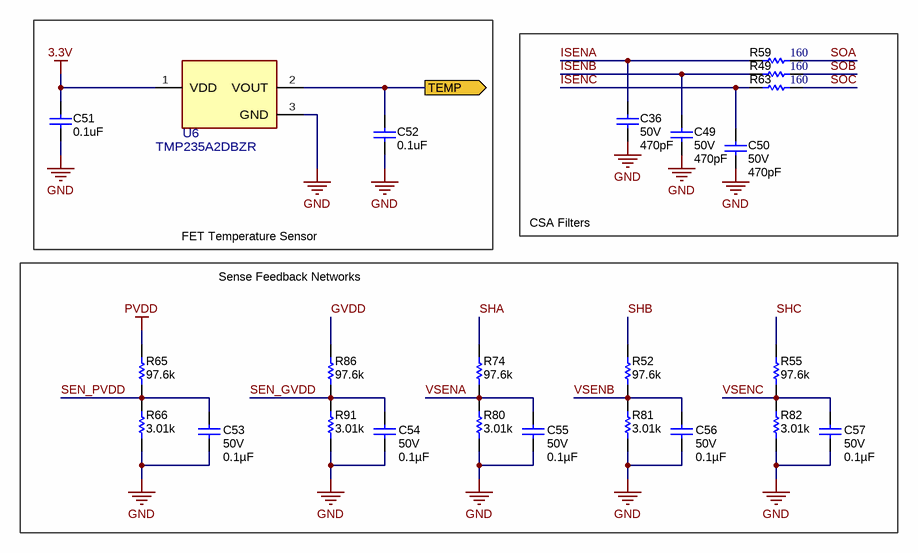
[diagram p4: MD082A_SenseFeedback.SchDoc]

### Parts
C36  VDC_V: 50V  ValueDisplayed: 470pF  [0805L]  (hidden comment: C0805C471K5RAC7800)
C49  VDC_V: 50V  ValueDisplayed: 470pF  [0805L]  (hidden comment: C0805C471K5RAC7800)
C50  VDC_V: 50V  ValueDisplayed: 470pF  [0805L]  (hidden comment: C0805C471K5RAC7800)
C51  ValueDisplayed: 0.1uF  [0603L]  (hidden comment: C0603C104J4RAC7867)
C52  ValueDisplayed: 0.1uF  [0603L]  (hidden comment: C0603C104J4RAC7867)
C53  Value2: 50V  ValueDisplayed: 0.1µF  [0603L]  (hidden comment: C0603C104K5RACAUTO)
C54  Value2: 50V  ValueDisplayed: 0.1µF  [0603L]  (hidden comment: C0603C104K5RACAUTO)
C55  Value2: 50V  ValueDisplayed: 0.1µF  [0603L]  (hidden comment: C0603C104K5RACAUTO)
C56  Value2: 50V  ValueDisplayed: 0.1µF  [0603L]  (hidden comment: C0603C104K5RACAUTO)
C57  Value2: 50V  ValueDisplayed: 0.1µF  [0603L]  (hidden comment: C0603C104K5RACAUTO)
R49  ValueDisplayed: 160  [0603L]  (hidden comment: RT0603DRE07160RL)
R52  ValueDisplayed: 97.6k  [0603L]  (hidden comment: CRCW060397K6FKEA)
R55  ValueDisplayed: 97.6k  [0603L]  (hidden comment: CRCW060397K6FKEA)
R59  ValueDisplayed: 160  [0603L]  (hidden comment: RT0603DRE07160RL)
R63  ValueDisplayed: 160  [0603L]  (hidden comment: RT0603DRE07160RL)
R65  ValueDisplayed: 97.6k  [0603L]  (hidden comment: CRCW060397K6FKEA)
R66  ValueDisplayed: 3.01k  [0603L]  (hidden comment: CRCW06033K01FKEA)
R74  ValueDisplayed: 97.6k  [0603L]  (hidden comment: CRCW060397K6FKEA)
R80  ValueDisplayed: 3.01k  [0603L]  (hidden comment: CRCW06033K01FKEA)
R81  ValueDisplayed: 3.01k  [0603L]  (hidden comment: CRCW06033K01FKEA)
R82  ValueDisplayed: 3.01k  [0603L]  (hidden comment: CRCW06033K01FKEA)
R86  ValueDisplayed: 97.6k  [0603L]  (hidden comment: CRCW060397K6FKEA)
R91  ValueDisplayed: 3.01k  [0603L]  (hidden comment: CRCW06033K01FKEA)
U6  TMP235A2DBZR  [DBZ0003A-MFG]

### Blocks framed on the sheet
FET Temperature Sensor: C51 C52 U6
CSA Filters: C36 C49 C50 R49 R59 R63
Sense Feedback Networks: C53-C57 R52 R55 R65 R66 R74 R80-R82 R86 R91

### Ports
TEMP (out)

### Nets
3.3V: C51.1 U6.1(VDD)
GND: C36.2 C49.2 C50.2 C51.2 C52.2 C53.1 C54.1 C55.1 C56.1 C57.1 R66.1 R80.1 R81.1 R82.1 R91.1 U6.3(GND)
GVDD: R86.2
PVDD: R65.2
ISENA: C36.1 R59.1
ISENB: C49.1 R49.1
ISENC: C50.1 R63.1
SEN_GVDD: C54.2 R86.1 R91.2
SEN_PVDD: C53.2 R65.1 R66.2
SHA: R74.2
SHB: R52.2
SHC: R55.2
SOA: R59.2
SOB: R49.2
SOC: R63.2
TEMP: C52.1 U6.2(VOUT) ; port TEMP
VSENA: C55.2 R74.1 R80.2
VSENB: C56.2 R52.1 R81.2
VSENC: C57.2 R55.1 R82.2

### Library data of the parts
C36 C49 C50 = CMP-0007796-3: CAP, CERM, 470 pF, 50 V, +/- 10%, X7R, 0805; Manufacturer: Kemet; TaMin_C: -55°C; ESR_ohm: 0.688; Polarized: N; SizeAreaWB_mm2: 6.75; Value1: 0.688 ohm; U/M: EA; Value: 470pF; TaMax_C: 125°C; SizeZ_mm: 1.45; SizeX_mm: 2; SizeY_mm: 1.25; Cap_Case: 0805; SizeArea_mm2: 2.5; IRMS_A: 213mA; AEC Category: Q200
C51 C52 = CMP-0006857-5: as C32 on sheet MD082A_Driver
C53-C57 = CMP-0079602-1: CAP, CERM, 0.1 µF, 50 V,+/- 10%, X7R, AEC-Q200 Grade 1, 0603; Manufacturer: Kemet; TaMin_C: -55°C; Polarized: N; SizeAreaWB_mm2: 4.68; U/M: EA; Value: 0.1uF; TaMax_C: 125°C; SizeZ_mm: 1; SizeX_mm: 1.6; SizeY_mm: 0.8; Cap_Case: 0603; SizeArea_mm2: 1.28; AEC Qualified: Y; Cap_F: 100nF; AEC Category: Q200
R49 R59 R63 = CMP-0024720-2: RES, 160, 0.5%, 0.1 W, 0603; Manufacturer: Yageo America; Power_W: 100mW; TempCo: 50 ppm/C; Value_Code: 160R; U/M: EA; Value: 160; EIA_Code: E192; SizeX_mm: 1.6; SizeY_mm: 0.8; SizeZ_mm: 1; Value2: 0.1W; SizeArea_mm2: 1.28; VDC_V: 75V; AEC Category: Q200
R52 R55 R65 R74 R86 = CMP-0022663-4: RES, 97.6 k, 1%, 0.1 W, AEC-Q200 Grade 0, 0603; Manufacturer: Vishay-Dale; Power_W: 100mW; TempCo: 100 ppm/C; Value_Code: 97k6; Value: 97.6k; EIA_Code: E96; SizeX_mm: 1.6; SizeY_mm: 0.8; SizeZ_mm: 1; Value2: 0.1W; SizeArea_mm2: 1.28; AEC Qualified: Y; VDC_V: 75V; AEC Category: Q200; AEC Grade: 0
R66 R80-R82 R91 = CMP-0022371-4: RES, 3.01 k, 1%, 0.1 W, AEC-Q200 Grade 0, 0603; Manufacturer: Vishay-Dale; Power_W: 100mW; TempCo: 100 ppm/C; Value_Code: 3k01; Value: 3.01k; EIA_Code: E96; SizeX_mm: 1.6; SizeY_mm: 0.8; SizeZ_mm: 1; Value2: 0.1W; SizeArea_mm2: 1.28; AEC Qualified: Y; VDC_V: 75V; AEC Category: Q200; AEC Grade: 0
U6 = CMP-0088337-2: Temperature Sensor Analog, Local -40°C ~ 150°C 10mV/°C SOT-23-3; Manufacturer: Texas Instruments; Accuracy: 0.5%; AEC Qualified: No; Operating Supply Current: 9uA; Sensor Output: Analog Voltage; TJmax_C: +150°C; SizeZ_mm: 1.12mm; Max Supply Voltage: 5.5V; Standoff Height: 0.01mm; Min Supply Voltage: 2.3V; AEC Category: Q200; CompType: IC

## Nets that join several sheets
3.3V: MD082A_Driver (5 pins), MD082A_Power (9 pins), MD082A_SenseFeedback (C51.1 U6.1)
5V: MD082A_Driver (5V_EXT.1 R7.2), MD082A_Power (J12.3)
GND: MD082A_Driver (9 pins), MD082A_HalfBridges (20 pins), MD082A_Power (23 pins), MD082A_SenseFeedback (16 pins)
GVDD: MD082A_Driver (C5.1 U1.30), MD082A_Power (GVDD.1), MD082A_SenseFeedback (R86.2)
PVDD: MD082A_Driver (J1.3), MD082A_HalfBridges (PVDD_EXT.1 R18.2), MD082A_Power (J6.1 PVDD.1), MD082A_SenseFeedback (R65.2)
PVDD_BUCK: MD082A_Driver (J1.1), MD082A_Power (5 pins)
VMOTOR: MD082A_HalfBridges (14 pins), MD082A_Power (F1.1)
GHA: MD082A_Driver (U1.38), MD082A_HalfBridges (R28.1)
GHB: MD082A_Driver (U1.43), MD082A_HalfBridges (R29.1)
GHC: MD082A_Driver (U1.48), MD082A_HalfBridges (R30.1)
GLA: MD082A_Driver (U1.39), MD082A_HalfBridges (R34.1)
GLB: MD082A_Driver (U1.42), MD082A_HalfBridges (R35.1)
GLC: MD082A_Driver (U1.1), MD082A_HalfBridges (R36.1)
HALL_A: MD082A_Driver (J9.13), MD082A_Power (C39.1 J11.2 R46.2)
HALL_B: MD082A_Driver (J9.15), MD082A_Power (C38.1 J11.3 R47.2)
HALL_C: MD082A_Driver (R8.1 R10.1), MD082A_Power (C37.1 J11.4 R48.2)
ISENA: MD082A_Driver (J8.14), MD082A_SenseFeedback (C36.1 R59.1)
ISENB: MD082A_Driver (J8.16), MD082A_SenseFeedback (C49.1 R49.1)
ISENC: MD082A_Driver (J8.18), MD082A_SenseFeedback (C50.1 R63.1)
nFAULT: MD082A_Driver (J8.19 R4.2 U1.22), MD082A_Power (R14.1)
SEN_GVDD: MD082A_Driver (J8.20), MD082A_Power (U4.1), MD082A_SenseFeedback (C54.2 R86.1 R91.2)
SEN_PVDD: MD082A_Driver (J8.12), MD082A_Power (U5.4), MD082A_SenseFeedback (C53.2 R65.1 R66.2)
SHA: MD082A_Driver (C6.1 U1.37), MD082A_HalfBridges (R37.1), MD082A_SenseFeedback (R74.2)
SHB: MD082A_Driver (C7.1 U1.44), MD082A_HalfBridges (R38.1), MD082A_SenseFeedback (R52.2)
SHC: MD082A_Driver (C8.1 U1.47), MD082A_HalfBridges (R56.1), MD082A_SenseFeedback (R55.2)
SLA: MD082A_Driver (U1.40), MD082A_HalfBridges (6 pins)
SLB: MD082A_Driver (U1.41), MD082A_HalfBridges (7 pins)
SLC: MD082A_Driver (U1.2), MD082A_HalfBridges (6 pins)
SNA: MD082A_Driver (U1.4), MD082A_HalfBridges (C33.2 C48.1 R45.1)
SNB: MD082A_Driver (U1.6), MD082A_HalfBridges (C41.1 C42.2 R54.1)
SNC: MD082A_Driver (U1.8), MD082A_HalfBridges (C43.2 C47.1 R53.1)
SOA: MD082A_Driver (U1.26), MD082A_SenseFeedback (R59.2)
SOB: MD082A_Driver (U1.25), MD082A_SenseFeedback (R49.2)
SOC: MD082A_Driver (U1.24), MD082A_SenseFeedback (R63.2)
SPA: MD082A_Driver (U1.3), MD082A_HalfBridges (C33.1 C45.1 R11.1)
SPB: MD082A_Driver (U1.5), MD082A_HalfBridges (C40.1 C42.1 R32.1)
SPC: MD082A_Driver (U1.7), MD082A_HalfBridges (C43.1 C46.1 R50.1)
TEMP: MD082A_Driver (J8.9), MD082A_SenseFeedback (C52.1 U6.2)
VDRAIN: MD082A_Driver (C4.2 U1.35), MD082A_HalfBridges (R39.1)
VSENA: MD082A_Driver (J8.6), MD082A_Power (U5.1), MD082A_SenseFeedback (C55.2 R74.1 R80.2)
VSENB: MD082A_Driver (J8.8), MD082A_Power (U5.6), MD082A_SenseFeedback (C56.2 R52.1 R81.2)
VSENC: MD082A_Driver (J8.10), MD082A_Power (U5.3), MD082A_SenseFeedback (C57.2 R55.1 R82.2)

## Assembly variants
001: not fitted C12 C13 C14 C15 C17 C19 C24 C25 C26 C27 C28 C29 FID1 FID2 FID3 R6 R10 R25 R26 R27 R40 R41 R42 R43 R44
002: not fitted C12 C13 C14 C15 C17 C19 C24 C25 C26 C27 C28 C29 FID1 FID2 FID3 R6 R10 R25 R26 R27 R40 R41 R42 R43 R44; alternate parts U1 -> CMP-0120171-1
